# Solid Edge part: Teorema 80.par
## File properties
Title: Terorema 80
Author: f.barsotti
Template: Normal.par
Last saved by: i.fialdini
Revision: 35
Application: Solid Edge
Tipo di contenuto documento: 0
Precisione: 0.990
Document Number: 8031-80
Revision: 0
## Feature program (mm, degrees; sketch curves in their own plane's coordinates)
sketch for "ProtrusioneEstrusa_1" plane through (0, 0, 0) normal (0, 0, 1) x-axis (1, 0, 0)
  line (-195, -402.5) -> (195, -402.5)
  line (195, -402.5) -> (195, 402.5)
  line (195, 402.5) -> (-195, 402.5)
  line (-195, 402.5) -> (-195, -402.5)
  dimension (linear) = 195
  dimension (linear) = 195
extrude "ProtrusioneEstrusa_1" add finite 135 along +normal
lofted cutout "unnamed LoftedCutout 1"
sketch for "Foro_1" plane through (12.5, 0.0692, 140) normal (0, 0, 1) x-axis (0, -1, 0)
  hole centre (0.0692, -12.5) bore radius 25
hole "Foro_1" diameter 50 through
fillet "Rotondo_7" radius 5
fillet "Rotondo_14" radius 5
fillet "Rotondo_17" radius 15
fillet "Rotondo_18" radius 6
fillet "Rotondo_19" radius 6
fillet "Rotondo_21" radius 15
fillet "Rotondo_26" radius 6
sketch for "Foro_6" plane through (0, 0, 135) normal (0, 0, 1) x-axis (0, 1, 0)
  hole centre (-380.5, -173) bore radius 8
  dimension (linear) = 380.5
  dimension (linear) = 380.5
hole "Foro_6" diameter 16 finite
sketch for "unnamed Hole 1" plane through (0, 0, 135) normal (0, 0, 1) x-axis (0, 1, 0)
  hole centre (380.5, -173) bore radius 8
hole "unnamed Hole 1" finite
pattern "unnamed Pattern 1" of "Foro_6", "unnamed Hole 1"
lofted cutout "unnamed LoftedCutout 2"
fillet "Rotondo_38" radius 20
fillet "Rotondo_39" radius 20
sketch for "unnamed Protrusion 1" #1 plane through (0, 0, 100) normal (0, 0, 1) x-axis (0, -1, 0)
  circle centre (0, 0) radius 35
sketch for "unnamed Protrusion 1" #2 plane through (0, 0, 100) normal (0, 0, 1) x-axis (0, -1, 0)
  circle centre (0, 0) radius 25
extrude "unnamed Protrusion 1" add to key point along +normal
fillet "Rotondo_40" radius 10
fillet "Rotondo_41" radius 2
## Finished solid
Body 1: solid body, 76 faces, 153 edges, 80 vertices.
  Faces by surface: cylinder 32, plane 20, blend 12, torus 8, sphere 4
  Edges by curve: line 64, circle 61, ellipse 28
Bounding box of the edges (mm; curved faces can reach further): 390.000 x 805.000 x 135.000, from (-195, -402.5, 0) to (195, 402.5, 135).
Cylindrical faces by radius (mm): R5 x6, R6 x10, R8 x2, R15 x4, R20 x8, R25 x1, R35 x1
Toroidal faces (ring radius, tube radius in mm): R1 r5 x4, R27 r2 x1, R33 r2 x1, R40 r15 x1, R45 r10 x1
Spherical faces by radius (mm): R20 x4
Planar faces by outward normal: +x 2, +y 1, +z 5, -x 1, -y 1, -z 3, oblique 7
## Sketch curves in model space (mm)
line (-149, -356.5, 100) -> (149, -356.5, 100)
line (149, -356.5, 100) -> (149, 356.5, 100)
line (149, 356.5, 100) -> (-149, 356.5, 100)
line (-149, 356.5, 100) -> (-149, -356.5, 100)
line (-160, -367.5, 135) -> (160, -367.5, 135)
line (160, -367.5, 135) -> (160, 367.5, 135)
line (160, 367.5, 135) -> (-160, 367.5, 135)
line (-160, 367.5, 135) -> (-160, -367.5, 135)
line (163, -375, 95) -> (-180, -375, 95)
line (-180, -375, 95) -> (-180, 375, 95)
line (-180, 375, 95) -> (163, 375, 95)
line (163, 375, 95) -> (163, -375, 95)
line (183, -390.5, 0) -> (-180, -390.5, 0)
line (-180, -390.5, 0) -> (-180, 390.5, 0)
line (-180, 390.5, 0) -> (183, 390.5, 0)
line (183, 390.5, 0) -> (183, -390.5, 0)
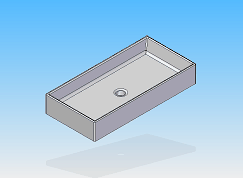
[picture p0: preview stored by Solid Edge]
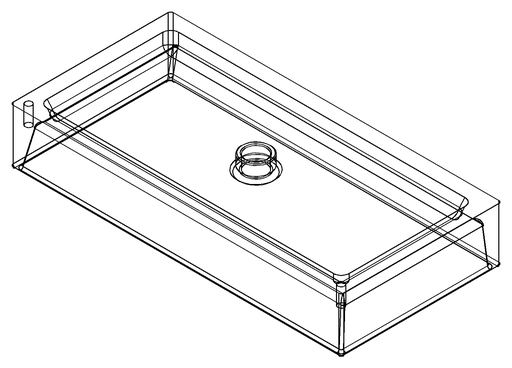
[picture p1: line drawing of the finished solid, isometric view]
